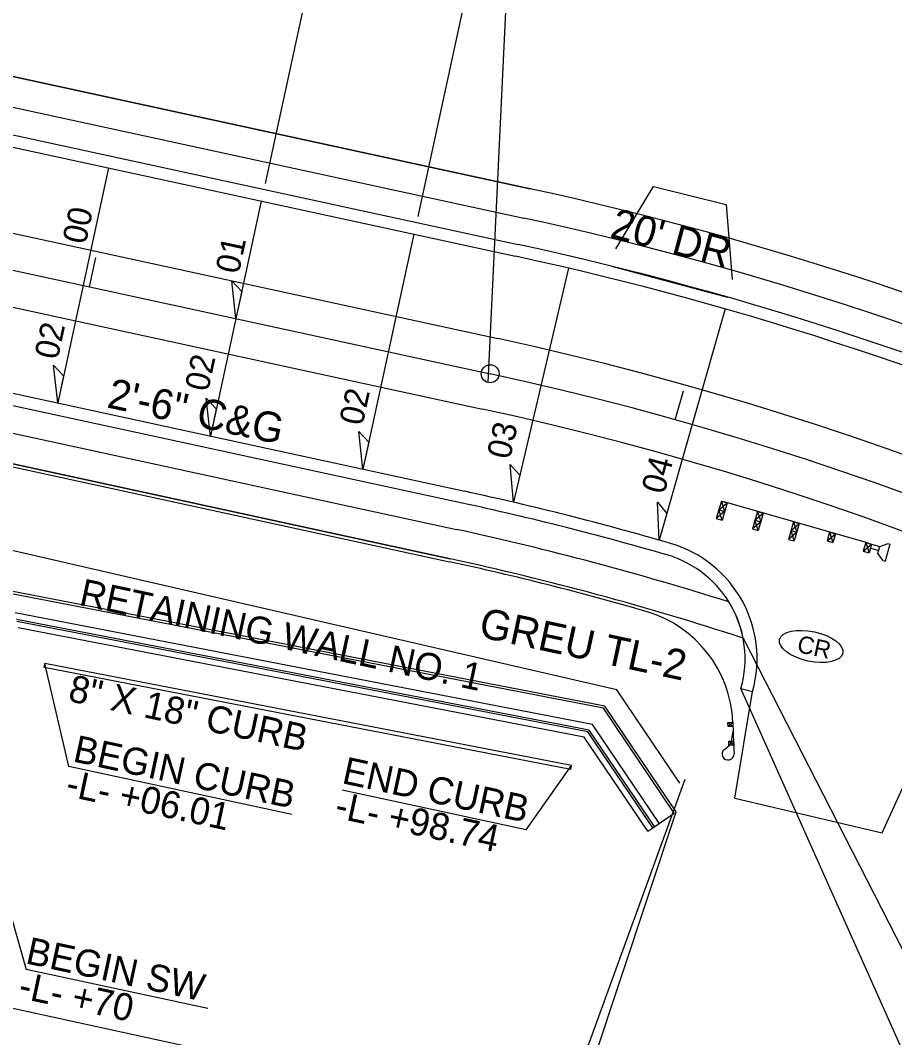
# Model space of a CAD drawing. Extents: x 1762196 to 1766326, y 709922 to 713142.
# Drawn here: x 1762967.8 to 1763113.4, y 712473.4 to 712642.7 of the extents above; entities that cross this region are included whole.
import ezdxf

# ---------------------------------------------------------------- set-up
doc = ezdxf.new("R2010")
doc.units = 0
for name, color, linetype in [('Old_Level_2', 7, 'Continuous'), ('Old_Level_3', 7, 'Continuous'), ('Pattern 1', 7, 'Continuous'), ('Pattern 2', 7, 'Continuous'), ('Pattern 3', 7, 'Continuous'), ('Pattern 4', 7, 'Continuous'), ('Pattern 5', 7, 'Continuous'), ('Prop Conc 2ft 6in Curb and Gutter', 7, 'Continuous'), ('Prop Conc Valley Gutter', 7, 'Continuous'), ('Prop Dimension', 7, 'Continuous'), ('Prop EOT', 7, 'Continuous'), ('Prop Fence Chain Link', 7, 'Continuous'), ('Prop GRAU CAT1 Cell', 7, 'Continuous'), ('Prop Guardrail', 7, 'Continuous'), ('Prop Guardrail Anchor Unit CELL', 7, 'Continuous'), ('Prop Horizontal Alignment', 7, 'Continuous'), ('Prop Horizontal Alignment Station Label', 7, 'Continuous'), ('Prop Horizontal Alignment Tick Small', 7, 'Continuous'), ('Prop Lane Lines', 7, 'Continuous'), ('Prop Structure Anchor Unit CELL', 7, 'Continuous'), ('Prop Superelevation  Arrow CELL', 7, 'Continuous'), ('Prop Superelevation Label', 7, 'Continuous'), ('Temp Shoring', 7, 'Continuous')]:
    doc.layers.add(name, color=color, linetype=linetype)

msp = doc.modelspace()

# ---------------------------------------------------------------- linework, layer by layer
at = {"layer": 'Old_Level_2'}
for p, q in [((1762971.79, 712535.01), (1762971.91, 712535.67)), ((1763059.59, 712518.73), (1762971.91, 712535.67)), ((1763059.46, 712518.07), (1763059.59, 712518.73))]:
    msp.add_line(p, q, dxfattribs=at)
at = {"layer": 'Old_Level_3'}
for p, q in [((1763066.99, 712604.69), (1763073.25, 712615.06)), ((1763073.25, 712615.06), (1763085.33, 712612.04)), ((1763085.33, 712612.04), (1763086.31, 712599.54)), ((1763059.46, 712518.07), (1762971.79, 712535.01))]:
    msp.add_line(p, q, dxfattribs=at)
at = {"layer": 'Pattern 1'}
for p, q in [((1763052.73, 712614.67), (1762956.72, 712635.5)), ((1762955.66, 712630.61), (1763051.67, 712609.78)), ((1762944.42, 712578.82), (1763040.44, 712557.99)), ((1763039.38, 712553.1), (1762943.36, 712573.93))]:
    msp.add_line(p, q, dxfattribs=at)
for centre, radius, start, end in [((1762933.05, 712063), 564.5, 53.4772, 77.7598), ((1762933.05, 712063), 559.5, 53.4772, 77.7598), ((1762933.05, 712063), 506.5, 72.4483, 77.7598), ((1762933.05, 712063), 501.5, 71.985, 77.7598), ((1763070.48, 712536.46), 18, 11.074, 31.7166)]:
    msp.add_arc(centre, radius, start, end, dxfattribs=at)
at = {"layer": 'Pattern 2'}
for p, q in [((1762956.72, 712635.5), (1763052.73, 712614.67)), ((1762955.66, 712630.61), (1763051.67, 712609.78)), ((1762944.42, 712578.82), (1763040.44, 712557.99)), ((1762943.36, 712573.93), (1763039.38, 712553.1))]:
    msp.add_line(p, q, dxfattribs=at)
for centre, radius, start, end in [((1762933.05, 712063), 564.5, 53.4772, 77.7598), ((1762933.05, 712063), 559.5, 53.4772, 77.7598), ((1762933.05, 712063), 506.5, 72.4483, 77.7598), ((1762933.05, 712063), 501.5, 71.985, 77.7598), ((1763070.48, 712536.46), 18, 11.074, 31.7166)]:
    msp.add_arc(centre, radius, start, end, dxfattribs=at)
at = {"layer": 'Pattern 3'}
for p, q in [((1763062.32, 712524.31), (1762967.28, 712542.67)), ((1763061.72, 712523.41), (1762967.5, 712541.61)), ((1763072.27, 712507.81), (1763061.72, 712523.41)), ((1763073.1, 712508.37), (1763062.32, 712524.31)), ((1763072.27, 712507.81), (1763073.1, 712508.37))]:
    msp.add_line(p, q, dxfattribs=at)
at = {"layer": 'Pattern 4'}
msp.add_line((1763066.22, 712601.79), (1763085.54, 712596.64), dxfattribs=at)
at = {"layer": 'Pattern 5'}
msp.add_ellipse((1763099.49, 712538.52), major_axis=(5.26, -1.13), ratio=0.462467, dxfattribs=at)
at = {"layer": 'Prop Conc 2ft 6in Curb and Gutter'}
for p, q in [((1762954.71, 712626.21), (1763050.72, 712605.39)), ((1762945.38, 712583.21), (1763041.39, 712562.39)), ((1763087.8, 712531.55), (1763089.73, 712531.01))]:
    msp.add_line(p, q, dxfattribs=at)
for centre, radius, start, end in [((1762933.05, 712063), 555, 53.4772, 77.7598), ((1762933.05, 712063), 511, 73.8134, 77.7598), ((1763070.48, 712536.46), 18, 344.1825, 73.8134)]:
    msp.add_arc(centre, radius, start, end, dxfattribs=at)
at = {"layer": 'Prop Conc Valley Gutter'}
for p, q in [((1763064.9, 712528.23), (1762966.11, 712547.31)), ((1763063.11, 712525.52), (1762966.99, 712544.09)), ((1763062.52, 712524.61), (1762967.21, 712543.03)), ((1763076.69, 712510.8), (1763064.9, 712528.23)), ((1763074.2, 712509.12), (1763063.11, 712525.52)), ((1763073.38, 712508.56), (1763062.52, 712524.61)), ((1763073.1, 712508.37), (1763076.69, 712510.8))]:
    msp.add_line(p, q, dxfattribs=at)
at = {"layer": 'Prop Dimension'}
for p, q in [((1762943.36, 712573.93), (1762968.83, 712484.79)), ((1763088.15, 712539.92), (1763129.2, 712459.66)), ((1762975.9, 712518.56), (1762971.91, 712535.67)), ((1763127.11, 712443.61), (1763087.8, 712531.55)), ((1763013.01, 712510.58), (1762975.9, 712518.56)), ((1763052.03, 712508.03), (1763059.59, 712518.73)), ((1763078.48, 712516.39), (1763032.33, 712389.96)), ((1763052.03, 712508.03), (1763021.41, 712514.62)), ((1763041.21, 712403.56), (1763077.03, 712511.03)), ((1762924.6, 712487.44), (1763020.61, 712466.61)), ((1762999.04, 712478.3), (1762968.83, 712484.79))]:
    msp.add_line(p, q, dxfattribs=at)
at = {"layer": 'Prop EOT'}
for p, q in [((1762954.28, 712624.26), (1763050.29, 712603.43)), ((1762945.8, 712585.17), (1763041.81, 712564.34)), ((1763086.78, 712513.28), (1763089.73, 712531.01)), ((1763111.29, 712507.5), (1763115.87, 712517.5)), ((1763086.78, 712513.28), (1763111.29, 712507.5))]:
    msp.add_line(p, q, dxfattribs=at)
for centre, radius, start, end in [((1762933.05, 712063), 553, 53.4772, 77.7598), ((1762933.05, 712063), 513, 73.8134, 77.7598), ((1763070.48, 712536.46), 20, 344.1825, 73.8134)]:
    msp.add_arc(centre, radius, start, end, dxfattribs=at)
at = {"layer": 'Prop Fence Chain Link'}
for p, q in [((1763065.15, 712528.6), (1762966.02, 712547.76)), ((1763077.03, 712511.03), (1763065.15, 712528.6))]:
    msp.add_line(p, q, dxfattribs=at)
at = {"layer": 'Prop GRAU CAT1 Cell'}
for p, q in [((1763085.63, 712525.89), (1763086.43, 712525.92)), ((1763085.66, 712525.19), (1763085.63, 712525.89)), ((1763086.46, 712525.22), (1763085.63, 712525.89)), ((1763086.43, 712525.92), (1763085.66, 712525.19)), ((1763086.46, 712525.22), (1763085.66, 712525.19)), ((1763086.43, 712525.92), (1763086.57, 712522.38)), ((1763086.43, 712525.92), (1763086.46, 712525.22)), ((1763086.17, 712522.45), (1763086.5, 712524.36)), ((1763085.03, 712521.39), (1763085.88, 712522.09)), ((1763085.75, 712522.78), (1763086.56, 712522.81)), ((1763085.78, 712522.08), (1763085.75, 712522.78)), ((1763086.59, 712522.11), (1763085.75, 712522.78)), ((1763086.56, 712522.81), (1763085.78, 712522.08)), ((1763086.59, 712522.11), (1763085.78, 712522.08)), ((1763086.56, 712522.81), (1763086.59, 712522.11)), ((1763086.58, 712522.25), (1763086.57, 712522.38)), ((1763086.57, 712522.38), (1763086.64, 712520.66))]:
    msp.add_line(p, q, dxfattribs=at)
msp.add_ellipse((1763085.65, 712520.62), major_axis=(0.992, 0.039), ratio=0.995379, start_param=2.210226, end_param=6.283185, dxfattribs=at)
at = {"layer": 'Prop Guardrail'}
msp.add_line((1762943.26, 712573.44), (1763039.27, 712552.61), dxfattribs=at)
for centre, radius, start, end in [((1762933.48, 712064.96), 499, 73.8826, 77.7598), ((1763066.45, 712525.13), 20, 2.2628, 73.8826)]:
    msp.add_arc(centre, radius, start, end, dxfattribs=at)
at = {"layer": 'Prop Guardrail Anchor Unit CELL'}
for p, q in [((1763084.53, 712562.7), (1763083.69, 712559.78)), ((1763084.11, 712561.24), (1763085.49, 712562.43)), ((1763084.53, 712562.7), (1763085.49, 712562.43)), ((1763084.53, 712562.7), (1763085.07, 712560.97)), ((1763085.49, 712562.43), (1763084.65, 712559.51)), ((1763109.05, 712555.69), (1763085.01, 712562.56)), ((1763085.07, 712560.97), (1763083.69, 712559.78)), ((1763084.11, 712561.24), (1763085.07, 712560.97)), ((1763084.65, 712559.51), (1763084.11, 712561.24)), ((1763090.54, 712560.98), (1763089.7, 712558.06)), ((1763090.12, 712559.52), (1763091.5, 712560.71)), ((1763090.54, 712560.98), (1763091.5, 712560.71)), ((1763090.54, 712560.98), (1763091.08, 712559.25)), ((1763091.5, 712560.71), (1763090.66, 712557.79)), ((1763083.69, 712559.78), (1763084.65, 712559.51)), ((1763091.08, 712559.25), (1763089.7, 712558.06)), ((1763090.12, 712559.52), (1763091.08, 712559.25)), ((1763090.66, 712557.79), (1763090.12, 712559.52)), ((1763096.55, 712559.26), (1763095.71, 712556.34)), ((1763096.13, 712557.8), (1763097.51, 712558.99)), ((1763096.55, 712559.26), (1763097.51, 712558.99)), ((1763096.55, 712559.26), (1763097.09, 712557.53)), ((1763097.51, 712558.99), (1763096.67, 712556.07)), ((1763089.7, 712558.06), (1763090.66, 712557.79)), ((1763097.09, 712557.53), (1763095.71, 712556.34)), ((1763096.13, 712557.8), (1763097.09, 712557.53)), ((1763096.67, 712556.07), (1763096.13, 712557.8)), ((1763102.56, 712557.54), (1763102.14, 712556.08)), ((1763102.14, 712556.08), (1763103.52, 712557.27)), ((1763102.56, 712557.54), (1763103.52, 712557.27)), ((1763102.56, 712557.54), (1763103.1, 712555.81)), ((1763103.52, 712557.27), (1763103.1, 712555.81)), ((1763095.71, 712556.34), (1763096.67, 712556.07)), ((1763102.14, 712556.08), (1763103.1, 712555.81)), ((1763108.56, 712555.82), (1763108.15, 712554.36)), ((1763108.15, 712554.36), (1763109.53, 712555.55)), ((1763108.56, 712555.82), (1763109.53, 712555.55)), ((1763108.56, 712555.82), (1763109.11, 712554.09)), ((1763109.53, 712555.55), (1763109.11, 712554.09)), ((1763109.52, 712555.54), (1763110.94, 712555.13)), ((1763110.94, 712555.13), (1763112.3, 712555.63)), ((1763112.6, 712555.55), (1763111.79, 712552.72)), ((1763112.3, 712555.63), (1763112.6, 712555.55)), ((1763108.15, 712554.36), (1763109.11, 712554.09)), ((1763110.74, 712554.44), (1763109.33, 712554.85)), ((1763110.6, 712553.96), (1763110.94, 712555.13)), ((1763111.49, 712552.81), (1763110.6, 712553.96)), ((1763111.49, 712552.81), (1763111.79, 712552.72))]:
    msp.add_line(p, q, dxfattribs=at)
at = {"layer": 'Prop Horizontal Alignment'}
msp.add_line((1762197.55, 712767.96), (1763046.05, 712583.89), dxfattribs=at)
msp.add_arc((1762933.05, 712063), 533, 36.325, 77.7598, dxfattribs=at)
at = {"layer": 'Prop Horizontal Alignment Station Label'}
msp.add_line((1763045.74, 712582.42), (1763053.9, 712753.61), dxfattribs=at)
msp.add_circle((1763046.05, 712583.89), 1.5, dxfattribs=at)
at = {"layer": 'Prop Horizontal Alignment Tick Small'}
for p, q in [((1762979.36, 712598.35), (1762980.42, 712603.24)), ((1763076.87, 712576.23), (1763078.22, 712581.05))]:
    msp.add_line(p, q, dxfattribs=at)
at = {"layer": 'Prop Lane Lines'}
for p, q in [((1762951.31, 712610.58), (1763047.33, 712589.75)), ((1762948.77, 712598.85), (1763044.78, 712578.02))]:
    msp.add_line(p, q, dxfattribs=at)
for radius in [539, 527]:
    msp.add_arc((1762933.05, 712063), radius, 36.325, 77.7598, dxfattribs=at)
at = {"layer": 'Prop Superelevation  Arrow CELL'}
for points in [[(1763003.71, 712593.07), (1763003.03, 712599.36), (1763004.69, 712597.59)], [(1762974.06, 712579.04), (1762973.38, 712585.33), (1762975.04, 712583.56)], [(1762999.47, 712573.53), (1762998.79, 712579.81), (1763000.45, 712578.05)], [(1763024.88, 712568.01), (1763024.2, 712574.3), (1763025.86, 712572.53)], [(1763049.96, 712562.5), (1763049.38, 712568.8), (1763051.01, 712567.01)], [(1763074.18, 712556.21), (1763073.9, 712562.53), (1763075.45, 712560.66)]]:
    msp.add_lwpolyline(points, close=True, dxfattribs=at)
at = {"layer": 'Prop Superelevation Label'}
for p, q in [((1763022.41, 712679.27), (1763008.59, 712615.55)), ((1763047.82, 712673.76), (1763034, 712610.04)), ((1762982.54, 712618.13), (1762974.06, 712579.04)), ((1763007.95, 712612.62), (1762999.47, 712573.53)), ((1763033.36, 712607.1), (1763024.88, 712568.01)), ((1763059.07, 712601.45), (1763049.96, 712562.5)), ((1763085.18, 712594.67), (1763074.18, 712556.21))]:
    msp.add_line(p, q, dxfattribs=at)
at = {"layer": 'Temp Shoring'}
for p, q in [((1763067.13, 712531.31), (1762964.79, 712554.87)), ((1763077.61, 712515.8), (1763067.13, 712531.31))]:
    msp.add_line(p, q, dxfattribs=at)

# ---------------------------------------------------------------- texts
at = {"layer": 'Pattern 5'}
msp.add_text('CR', height=2.88, rotation=347.8639, dxfattribs=at).set_placement((1763096.98, 712537.61))
at = {"layer": 'Prop Dimension'}
for s, height, rotation, p in [("20' DR", 5, 345.085, (1763065.82, 712606.67)), ('2\'-6" C&G', 5, 347.9451, (1762982.08, 712578.31)), ('RETAINING WALL NO. 1', 4.5, 347.8639, (1762977.47, 712545.44)), ('8" X 18" CURB', 4.5, 347.8639, (1762975.62, 712529.48)), ('BEGIN CURB', 4.5, 347.8639, (1762976.43, 712519.41)), ('END CURB', 4.5, 347.8639, (1763021.21, 712515.8)), ('-L- +06.01', 4.5, 347.8639, (1762975.2, 712513.7)), ('-L- +98.74', 4.5, 347.8639, (1763019.98, 712510.08)), ('BEGIN SW', 4.5, 347.8639, (1762968.55, 712485.82)), ('-L- +70', 4.5, 347.8639, (1762967.32, 712480.1))]:
    msp.add_text(s, height=height, rotation=rotation, dxfattribs=at).set_placement(p)
at = {"layer": 'Prop Structure Anchor Unit CELL'}
msp.add_text('GREU TL-2', height=5, rotation=347.8641, dxfattribs=at).set_placement((1763043.96, 712540.16))
at = {"layer": 'Prop Superelevation Label'}
for s, rotation, p in [('00', 77.8638, (1762978.72, 712605.29)), ('01', 77.8638, (1763004.2, 712600.36)), ('02', 77.8638, (1762974.07, 712586.11)), ('02', 77.8638, (1762999.1, 712580.79)), ('02', 77.8638, (1763024.8, 712575.13)), ('03', 77.2448, (1763049.35, 712569.51)), ('04', 75.3886, (1763075.04, 712563.71))]:
    msp.add_text(s, height=4, rotation=rotation, dxfattribs=at).set_placement(p)

doc.saveas('drawing.dxf')
